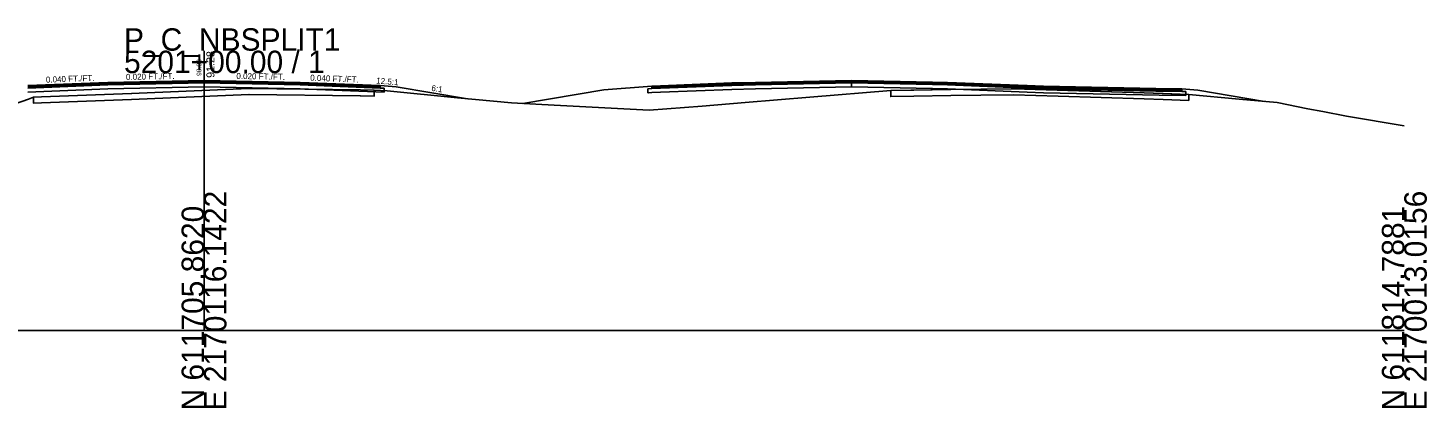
# Model space of a CAD drawing. Extents: x -26 to 1303, y -3010 to 12038.
# Drawn here: x 1128 to 1302.8, y 1490.3 to 1537.8 of the extents above; entities that cross this region are included whole.
import ezdxf

# ---------------------------------------------------------------- set-up
doc = ezdxf.new("R2010")
doc.units = 0
for name, color, linetype in [('RD_GPK_XS_Cell', 7, 'Continuous'), ('RD_XS_Base', 7, 'Continuous'), ('RD_XS_ExGround', 7, 'Continuous'), ('RD_XS_ExPaveRet', 7, 'Continuous'), ('RD_XS_Greenside', 7, 'Continuous'), ('RD_XS_Pave', 7, 'Continuous'), ('RD_XS_PaveOvlay_CP', 7, 'Continuous'), ('RD_XS_TieSlope', 7, 'Continuous'), ('RD_XS_TX_Elev_EX', 7, 'Continuous'), ('RD_XS_TX_Elev_PR', 7, 'Continuous'), ('RD_XS_TX_ShdSlope', 7, 'Continuous'), ('RD_XS_TX_Slope', 7, 'Continuous')]:
    doc.layers.add(name, color=color, linetype=linetype)

msp = doc.modelspace()

# ---------------------------------------------------------------- linework, layer by layer
at = {"layer": 'RD_GPK_XS_Cell'}
for p, q in [((1150, 1500), (1150, 1535)), ((1000, 1500), (1150, 1500)), ((1150, 1500), (1300, 1500))]:
    msp.add_line(p, q, dxfattribs=at)
at = {"layer": 'RD_XS_Base'}
for p, q in [((1138, 1530.72), (1128, 1530.32)), ((1128, 1529.82), (1138, 1530.22)), ((1150, 1530.96), (1138, 1530.72)), ((1138, 1530.72), (1138, 1530.72)), ((1138, 1530.22), (1150, 1530.46)), ((1138, 1530.22), (1138, 1530.22)), ((1150, 1530.96), (1150, 1531.12)), ((1150, 1531.12), (1150, 1531.12)), ((1150, 1531.12), (1150, 1531.12)), ((1150, 1531.12), (1150, 1530.46)), ((1150, 1530.46), (1150, 1530.96)), ((1150, 1530.96), (1150, 1530.96)), ((1150, 1530.96), (1150, 1530.96)), ((1150, 1530.96), (1150, 1530.96)), ((1162, 1530.72), (1150, 1530.96)), ((1150, 1530.46), (1150, 1530.46)), ((1150, 1530.46), (1150, 1530.46)), ((1150, 1530.46), (1162, 1530.22)), ((1172, 1530.32), (1162, 1530.72)), ((1162, 1530.22), (1172.5, 1529.8)), ((1164, 1530.64), (1164, 1530.64)), ((1164, 1530.14), (1164, 1530.14)), ((1172.5, 1530.3), (1172, 1530.32)), ((1172, 1530.32), (1172, 1530.32)), ((1172.5, 1529.8), (1172.5, 1530.3)), ((1172.5, 1530.3), (1172.5, 1530.3)), ((1205.53, 1530.24), (1205.47, 1530.24)), ((1205.47, 1530.24), (1205.47, 1529.79)), ((1205.97, 1530.26), (1205.53, 1530.24)), ((1207.06, 1530.3), (1205.97, 1530.26)), ((1215.97, 1530.66), (1207.06, 1530.3)), ((1207.06, 1529.8), (1215.97, 1530.16)), ((1218.9, 1530.72), (1215.97, 1530.66)), ((1215.97, 1530.16), (1218.9, 1530.22)), ((1230.9, 1530.96), (1218.9, 1530.72)), ((1218.9, 1530.22), (1230.9, 1530.46)), ((1230.9, 1530.98), (1230.9, 1531.12)), ((1230.9, 1531.12), (1230.9, 1530.55)), ((1230.9, 1530.96), (1230.9, 1530.98)), ((1230.9, 1530.96), (1230.9, 1530.96)), ((1241.03, 1530.75), (1230.9, 1530.96)), ((1230.9, 1530.96), (1230.9, 1530.96)), ((1230.9, 1530.53), (1230.9, 1530.96)), ((1230.9, 1530.55), (1230.9, 1530.46)), ((1230.9, 1530.46), (1230.9, 1530.53)), ((1230.9, 1530.46), (1241.03, 1530.25)), ((1242.9, 1530.72), (1241.03, 1530.75)), ((1241.03, 1530.25), (1242.9, 1530.22)), ((1252.87, 1530.32), (1242.9, 1530.72)), ((1242.9, 1530.22), (1252.87, 1529.82)), ((1254.9, 1530.23), (1252.87, 1530.32)), ((1268.96, 1529.95), (1254.9, 1530.23)), ((1272.21, 1529.89), (1268.96, 1529.95)), ((1272.61, 1529.88), (1272.21, 1529.89)), ((1272.71, 1529.88), (1272.61, 1529.88)), ((1272.71, 1529.47), (1272.71, 1529.88)), ((1205.47, 1529.79), (1205.47, 1529.74)), ((1205.47, 1529.74), (1205.53, 1529.74)), ((1205.53, 1529.74), (1205.97, 1529.76)), ((1205.97, 1529.76), (1207.06, 1529.8)), ((1252.87, 1529.82), (1254.9, 1529.73)), ((1254.9, 1529.73), (1269.36, 1529.44)), ((1269.36, 1529.44), (1272.71, 1529.38)), ((1272.71, 1529.38), (1272.71, 1529.47))]:
    msp.add_line(p, q, dxfattribs=at)
at = {"layer": 'RD_XS_ExGround'}
msp.add_lwpolyline([(1118.11, 1525.49), (1128.05, 1528.95), (1128.67, 1529.2), (1129.7, 1529.24), (1140.95, 1529.63), (1155.61, 1530.27), (1169.55, 1530.09), (1171.28, 1530.07), (1172.89, 1529.96), (1181.66, 1529.11), (1188.42, 1528.49), (1193.77, 1528.18), (1205.63, 1527.54), (1212.26, 1528.06), (1217.63, 1528.5), (1225.71, 1529.17), (1235.82, 1530.01), (1243.33, 1530.14), (1251.18, 1530.22), (1267.48, 1529.71), (1273.06, 1529.54), (1279.37, 1528.95), (1284.11, 1528.51), (1287.95, 1527.71), (1289.81, 1527.39), (1292.79, 1526.83), (1300, 1525.61)], dxfattribs=at)
at = {"layer": 'RD_XS_ExPaveRet'}
for p, q in [((1171.28, 1530.07), (1169.55, 1530.09)), ((1238.71, 1530.06), (1235.82, 1530.01)), ((1251.18, 1530.22), (1247.09, 1530.18)), ((1129.7, 1529.24), (1128.67, 1529.2)), ((1140.95, 1529.63), (1129.7, 1529.24)), ((1273.06, 1529.54), (1269.86, 1529.64))]:
    msp.add_line(p, q, dxfattribs=at)
for points in [[(1171.28, 1530.07), (1171.28, 1529.32), (1171.28, 1529.32), (1171.28, 1529.32), (1169.55, 1529.34), (1169.55, 1529.34), (1155.61, 1529.52), (1155.61, 1529.52), (1140.95, 1528.88), (1140.95, 1528.88), (1129.7, 1528.49), (1129.7, 1528.49), (1128.67, 1528.45), (1128.67, 1529.2), (1128.67, 1529.2), (1129.7, 1529.24), (1129.7, 1529.24), (1140.95, 1529.63), (1140.95, 1529.63), (1155.61, 1530.27), (1155.61, 1530.27), (1169.55, 1530.09), (1169.55, 1530.09), (1171.28, 1530.07), (1171.28, 1530.07)], [(1128.67, 1529.2), (1128.67, 1528.45), (1129.7, 1528.49), (1140.95, 1528.88), (1155.61, 1529.52), (1169.55, 1529.34), (1171.28, 1529.32), (1171.28, 1529.32), (1171.28, 1530.07), (1171.28, 1530.07)], [(1169.55, 1530.09), (1155.61, 1530.27), (1140.95, 1529.63)], [(1267.48, 1529.71), (1256.75, 1530.05), (1251.18, 1530.22), (1247.09, 1530.18), (1243.33, 1530.14), (1238.71, 1530.06), (1235.82, 1530.01), (1235.82, 1530.01), (1235.82, 1530.01), (1235.82, 1529.66), (1235.82, 1529.26), (1235.82, 1529.26), (1235.82, 1529.26), (1238.71, 1529.31), (1243.33, 1529.39), (1247.09, 1529.43), (1251.18, 1529.47), (1256.75, 1529.3), (1267.48, 1528.96), (1269.86, 1528.89), (1273.06, 1528.79), (1273.06, 1529.31), (1273.06, 1529.54), (1269.86, 1529.64), (1267.48, 1529.71)], [(1235.82, 1530.01), (1235.82, 1529.66), (1235.82, 1529.26), (1238.71, 1529.31), (1243.33, 1529.39), (1247.09, 1529.43), (1251.18, 1529.47), (1256.75, 1529.3), (1267.48, 1528.96), (1269.86, 1528.89), (1273.06, 1528.79), (1273.06, 1529.31), (1273.06, 1529.54)], [(1247.09, 1530.18), (1243.33, 1530.14), (1238.71, 1530.06)], [(1269.86, 1529.64), (1267.48, 1529.71), (1256.75, 1530.05), (1251.18, 1530.22)]]:
    msp.add_lwpolyline(points, dxfattribs=at)
at = {"layer": 'RD_XS_Greenside'}
for p, q in [((1174, 1530.48), (1182.93, 1528.99)), ((1199.97, 1530.1), (1189.85, 1528.41)), ((1274.21, 1530.05), (1282.55, 1528.65))]:
    msp.add_line(p, q, dxfattribs=at)
at = {"layer": 'RD_XS_Pave'}
for p, q in [((1138, 1531.04), (1128, 1530.64)), ((1138, 1530.88), (1128, 1530.48)), ((1128, 1530.48), (1138, 1530.88)), ((1128, 1530.32), (1138, 1530.72)), ((1150, 1531.28), (1138, 1531.04)), ((1150, 1531.12), (1138, 1530.88)), ((1138, 1530.88), (1150, 1531.12)), ((1138, 1531.04), (1138, 1531.04)), ((1138, 1530.72), (1150, 1530.96)), ((1138, 1530.88), (1138, 1530.88)), ((1138, 1530.88), (1138, 1530.88)), ((1138, 1530.72), (1138, 1530.72)), ((1162, 1531.04), (1150, 1531.28)), ((1150, 1531.28), (1150, 1531.28)), ((1150, 1531.28), (1150, 1531.28)), ((1150, 1530.96), (1150, 1531.12)), ((1150, 1531.12), (1150, 1531.12)), ((1150, 1531.12), (1150, 1531.12)), ((1150, 1531.12), (1150, 1531.12)), ((1150, 1531.12), (1150, 1531.12)), ((1150, 1531.12), (1162, 1530.88)), ((1162, 1530.88), (1150, 1531.12)), ((1150, 1531.12), (1150, 1531.12)), ((1150, 1531.12), (1150, 1531.12)), ((1150, 1531.12), (1150, 1530.96)), ((1150, 1530.96), (1150, 1530.96)), ((1150, 1530.96), (1150, 1530.96)), ((1150, 1530.96), (1162, 1530.72)), ((1172, 1530.64), (1162, 1531.04)), ((1162, 1530.88), (1172, 1530.48)), ((1172, 1530.48), (1162, 1530.88)), ((1162, 1530.72), (1172, 1530.32)), ((1164, 1530.96), (1164, 1530.96)), ((1164, 1530.8), (1164, 1530.8)), ((1164, 1530.8), (1164, 1530.8)), ((1164, 1530.64), (1164, 1530.64)), ((1172, 1530.48), (1172, 1530.64)), ((1172, 1530.64), (1172, 1530.64)), ((1172, 1530.32), (1172, 1530.48)), ((1172, 1530.48), (1172, 1530.48)), ((1207.06, 1530.62), (1205.97, 1530.58)), ((1205.97, 1530.58), (1205.97, 1530.44)), ((1207.06, 1530.46), (1205.97, 1530.42)), ((1205.97, 1530.42), (1207.06, 1530.46)), ((1205.97, 1530.44), (1205.97, 1530.42)), ((1205.97, 1530.42), (1205.97, 1530.28)), ((1205.97, 1530.26), (1207.06, 1530.3)), ((1205.97, 1530.28), (1205.97, 1530.26)), ((1215.97, 1530.98), (1207.06, 1530.62)), ((1215.97, 1530.82), (1207.06, 1530.46)), ((1207.06, 1530.46), (1215.97, 1530.82)), ((1207.06, 1530.3), (1215.97, 1530.66)), ((1218.9, 1531.03), (1215.97, 1530.98)), ((1218.9, 1530.88), (1215.97, 1530.82)), ((1215.97, 1530.82), (1218.9, 1530.88)), ((1215.97, 1530.66), (1218.9, 1530.72)), ((1230.9, 1531.27), (1218.9, 1531.03)), ((1230.9, 1531.12), (1218.9, 1530.88)), ((1218.9, 1530.88), (1230.9, 1531.12)), ((1218.9, 1530.72), (1230.9, 1530.96)), ((1241.03, 1531.07), (1230.9, 1531.27)), ((1230.9, 1530.98), (1230.9, 1531.12)), ((1230.9, 1531.12), (1241.03, 1530.91)), ((1241.03, 1530.91), (1230.9, 1531.12)), ((1230.9, 1531.12), (1230.9, 1531.12)), ((1230.9, 1531.12), (1230.9, 1531.12)), ((1230.9, 1531.12), (1230.9, 1530.98)), ((1230.9, 1530.96), (1230.9, 1530.98)), ((1230.9, 1530.98), (1230.9, 1530.96)), ((1230.9, 1530.96), (1230.9, 1530.96)), ((1230.9, 1530.96), (1230.9, 1530.96)), ((1230.9, 1530.96), (1241.03, 1530.75)), ((1242.9, 1531.03), (1241.03, 1531.07)), ((1241.03, 1530.91), (1242.9, 1530.87)), ((1242.9, 1530.87), (1241.03, 1530.91)), ((1241.03, 1530.75), (1242.9, 1530.72)), ((1252.87, 1530.63), (1242.9, 1531.03)), ((1242.9, 1530.87), (1252.87, 1530.48)), ((1252.87, 1530.48), (1242.9, 1530.87)), ((1242.9, 1530.72), (1252.87, 1530.32)), ((1254.9, 1530.55), (1252.87, 1530.63)), ((1252.87, 1530.48), (1254.9, 1530.39)), ((1254.9, 1530.39), (1252.87, 1530.48)), ((1252.87, 1530.32), (1254.9, 1530.23)), ((1268.96, 1530.27), (1254.9, 1530.55)), ((1254.9, 1530.39), (1268.96, 1530.11)), ((1268.96, 1530.11), (1254.9, 1530.39)), ((1254.9, 1530.23), (1268.96, 1529.95)), ((1272.21, 1530.21), (1268.96, 1530.27)), ((1268.96, 1530.11), (1272.21, 1530.05)), ((1272.21, 1530.05), (1268.96, 1530.11)), ((1268.96, 1529.95), (1272.21, 1529.89)), ((1272.21, 1530.08), (1272.21, 1530.21)), ((1272.21, 1530.05), (1272.21, 1530.08)), ((1272.21, 1529.92), (1272.21, 1530.05)), ((1272.21, 1529.89), (1272.21, 1529.92))]:
    msp.add_line(p, q, dxfattribs=at)
at = {"layer": 'RD_XS_PaveOvlay_CP'}
for p, q in [((1128, 1530.64), (1138, 1531.04)), ((1138, 1531.04), (1150, 1531.28)), ((1150, 1531.28), (1162, 1531.04)), ((1162, 1531.04), (1172, 1530.64)), ((1207.06, 1530.62), (1205.97, 1530.58)), ((1215.97, 1530.98), (1207.06, 1530.62)), ((1218.9, 1531.03), (1215.97, 1530.98)), ((1230.9, 1531.27), (1218.9, 1531.03)), ((1241.03, 1531.07), (1230.9, 1531.27)), ((1242.9, 1531.03), (1241.03, 1531.07)), ((1252.87, 1530.63), (1242.9, 1531.03)), ((1254.9, 1530.55), (1252.87, 1530.63)), ((1268.96, 1530.27), (1254.9, 1530.55)), ((1272.21, 1530.21), (1268.96, 1530.27))]:
    msp.add_line(p, q, dxfattribs=at)
at = {"layer": 'RD_XS_TieSlope'}
for p, q in [((1172, 1530.64), (1174, 1530.48)), ((1205.97, 1530.58), (1199.97, 1530.1)), ((1272.21, 1530.21), (1274.21, 1530.05))]:
    msp.add_line(p, q, dxfattribs=at)

# ---------------------------------------------------------------- texts
at = {"layer": 'RD_GPK_XS_Cell'}
for s, p in [('P_C_NBSPLIT1', (1140, 1535)), ('5201+00.00 / 1', (1140, 1532.2))]:
    msp.add_text(s, height=2.8, dxfattribs=at).set_placement(p)
for s, p in [('E 2170116.1422', (1152.8, 1490)), ('E 2170013.0156', (1302.8, 1490)), ('N 611705.8620', (1150, 1490)), ('N 611814.7881', (1300, 1490))]:
    msp.add_text(s, height=2.8, rotation=90, dxfattribs=at).set_placement(p)
at = {"layer": 'RD_XS_TX_Elev_EX'}
msp.add_text('90.03', height=0.6, rotation=90, dxfattribs=at).set_placement((1149.67, 1531.85))
at = {"layer": 'RD_XS_TX_Elev_PR'}
msp.add_text('91.28', height=1, rotation=90, dxfattribs=at).set_placement((1151.3, 1531.6))
at = {"layer": 'RD_XS_TX_ShdSlope'}
msp.add_text('12.5:1', height=0.75, rotation=355.4261, dxfattribs=at).set_placement((1171.5, 1530.89))
at = {"layer": 'RD_XS_TX_Slope'}
for s, rotation, p in [('0.040 FT./FT.', 2.2906, (1130.25, 1530.99)), ('0.020 FT./FT.', 1.1458, (1140.25, 1531.34)), ('0.020 FT./FT.', 358.8542, (1154.04, 1531.47)), ('0.040 FT./FT.', 357.7094, (1163.26, 1531.25)), ('6:1', 350.5377, (1178.37, 1529.99))]:
    msp.add_text(s, height=0.75, rotation=rotation, dxfattribs=at).set_placement(p)

doc.saveas('drawing.dxf')
